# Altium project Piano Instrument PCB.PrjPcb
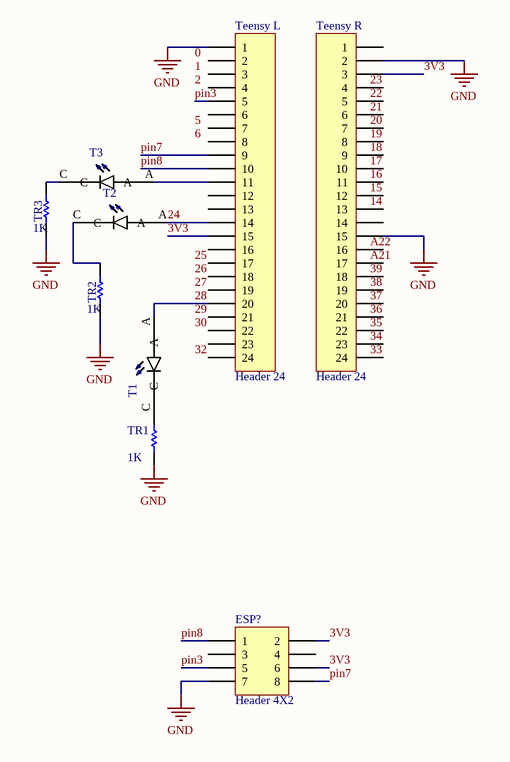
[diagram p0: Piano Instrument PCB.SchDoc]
1 sheet, 9 parts. Net scope: global (net labels, ports and power ports of the same name join across sheets).
Board file: Piano Instrument PCB.PcbDoc

## Sheet Piano Instrument PCB.SchDoc
size A4

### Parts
ESP  Header 4X2  [HDR2X4]
T1  LTL-1CHYE  [LED_LTL-1CHYE_LTL-1CHYE(Primary)]  (value not drawn)
T2  LTL-1CHYE  [LED_LTL-1CHYE_LTL-1CHYE(Primary)]  (value not drawn)
T3  LTL-1CHYE  [LED_LTL-1CHYE_LTL-1CHYE(Primary)]  (value not drawn)
Teensy_L  Header 24  [HDR1X24]
Teensy_R  Header 24  [HDR1X24]
TR1  value 1K  [AXIAL-0.5]
TR2  value 1K  [AXIAL-0.5]
TR3  value 1K  [AXIAL-0.5]

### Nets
GND: ESP.7 Teensy_L.1 Teensy_R.2 Teensy_R.15 TR1.1 TR2.1 TR3.1
3V3: ESP.2 ESP.6 Teensy_L.15 Teensy_R.3
24: T2.A Teensy_L.14
28: T1.A Teensy_L.20
pin3: ESP.5 Teensy_L.5
pin7: ESP.8 Teensy_L.9
pin8: ESP.1 Teensy_L.10
NetT1_C: T1.C TR1.2
NetT2_C: T2.C TR2.2
NetT3_A: T3.A Teensy_L.11
NetT3_C: T3.C TR3.2

Not connected (* = marked no-connect by the designer): ESP 3 4; Teensy_L 2 3 4 6 7 8 12 13 16 17 18 19 21 22 23 24; Teensy_R 1 4 5 6 7 8 9 10 11 12 13 14 16 17 18 19 20 21 22 23 24

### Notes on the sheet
- Labels drawn without touching a wire or pin: 0, 1, 2, 5, 6, 14, 15, 16, 17, 18, 19, 20, 21, 22, 23, 25, 26, 27, 29, 30, 32, 33, 34, 35, 36, 37, 38, 39, A21, A22

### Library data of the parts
ESP = Header 4X2: Header, 4-Pin, Dual row
T1-T3 = LTL-1CHYE: Yellow 3.1 mm 45Â° Tinted Clear 40 mcd 2.1 V LED Through Hole; MF: Lite-On
Teensy_L Teensy_R = Header 24: Header, 24-Pin
TR1-TR3 = Res Semi: Semiconductor Resistor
